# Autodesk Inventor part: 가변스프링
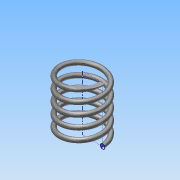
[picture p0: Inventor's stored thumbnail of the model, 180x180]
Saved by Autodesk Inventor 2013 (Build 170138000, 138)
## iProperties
Created: 2018-12
Part Number: 가변스프링
Material: 스테인리스강
Document SubType Name: Modeling
Designer: Administrator
Density: 8.08 g/cm^3
Mass: 7.0516 g
Surface Area: 17.7129 cm^2
Volume: 0.872722 cm^3
Author: Administrator
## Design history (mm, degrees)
sketch "스케치3"
  geometry: L1 (0, 0)-(9, 0); L2 (9, 0)-(9, 24.5); L3 (9, 24.5)-(0, 24.5); L4 (0, 24.5)-(0, 0); C1 r 1 at (9, 0)
  constraints: 8 end point, 2 parallel, 1 centre point, 1 coincident, 1 horizontal, 1 perpendicular
  dimensions: "d2" = 24.5 distance of L1.end L2.end (derived); "d4" = 18 diameter of L2 L4; "d5" = 2 diameter of C1
feature "코일1" pitch "d6" = 10; turns "d8" = 5; dims "d7" = 24.5 (= d2), "d9" = 0, angle "d10" = 90 deg, angle "d11" = 90 deg, "d12" = 0, "d13" = 0
sketch "스케치4"
  geometry: C1 r 14.844 at (0, 0); 1 further point
  constraints: 1 centre point, 1 coincident
extrude "돌출1" sketch "스케치4" distance "d14" = 24.5 (= d2); taper "d15" = 0 deg
node "솔리드1"
